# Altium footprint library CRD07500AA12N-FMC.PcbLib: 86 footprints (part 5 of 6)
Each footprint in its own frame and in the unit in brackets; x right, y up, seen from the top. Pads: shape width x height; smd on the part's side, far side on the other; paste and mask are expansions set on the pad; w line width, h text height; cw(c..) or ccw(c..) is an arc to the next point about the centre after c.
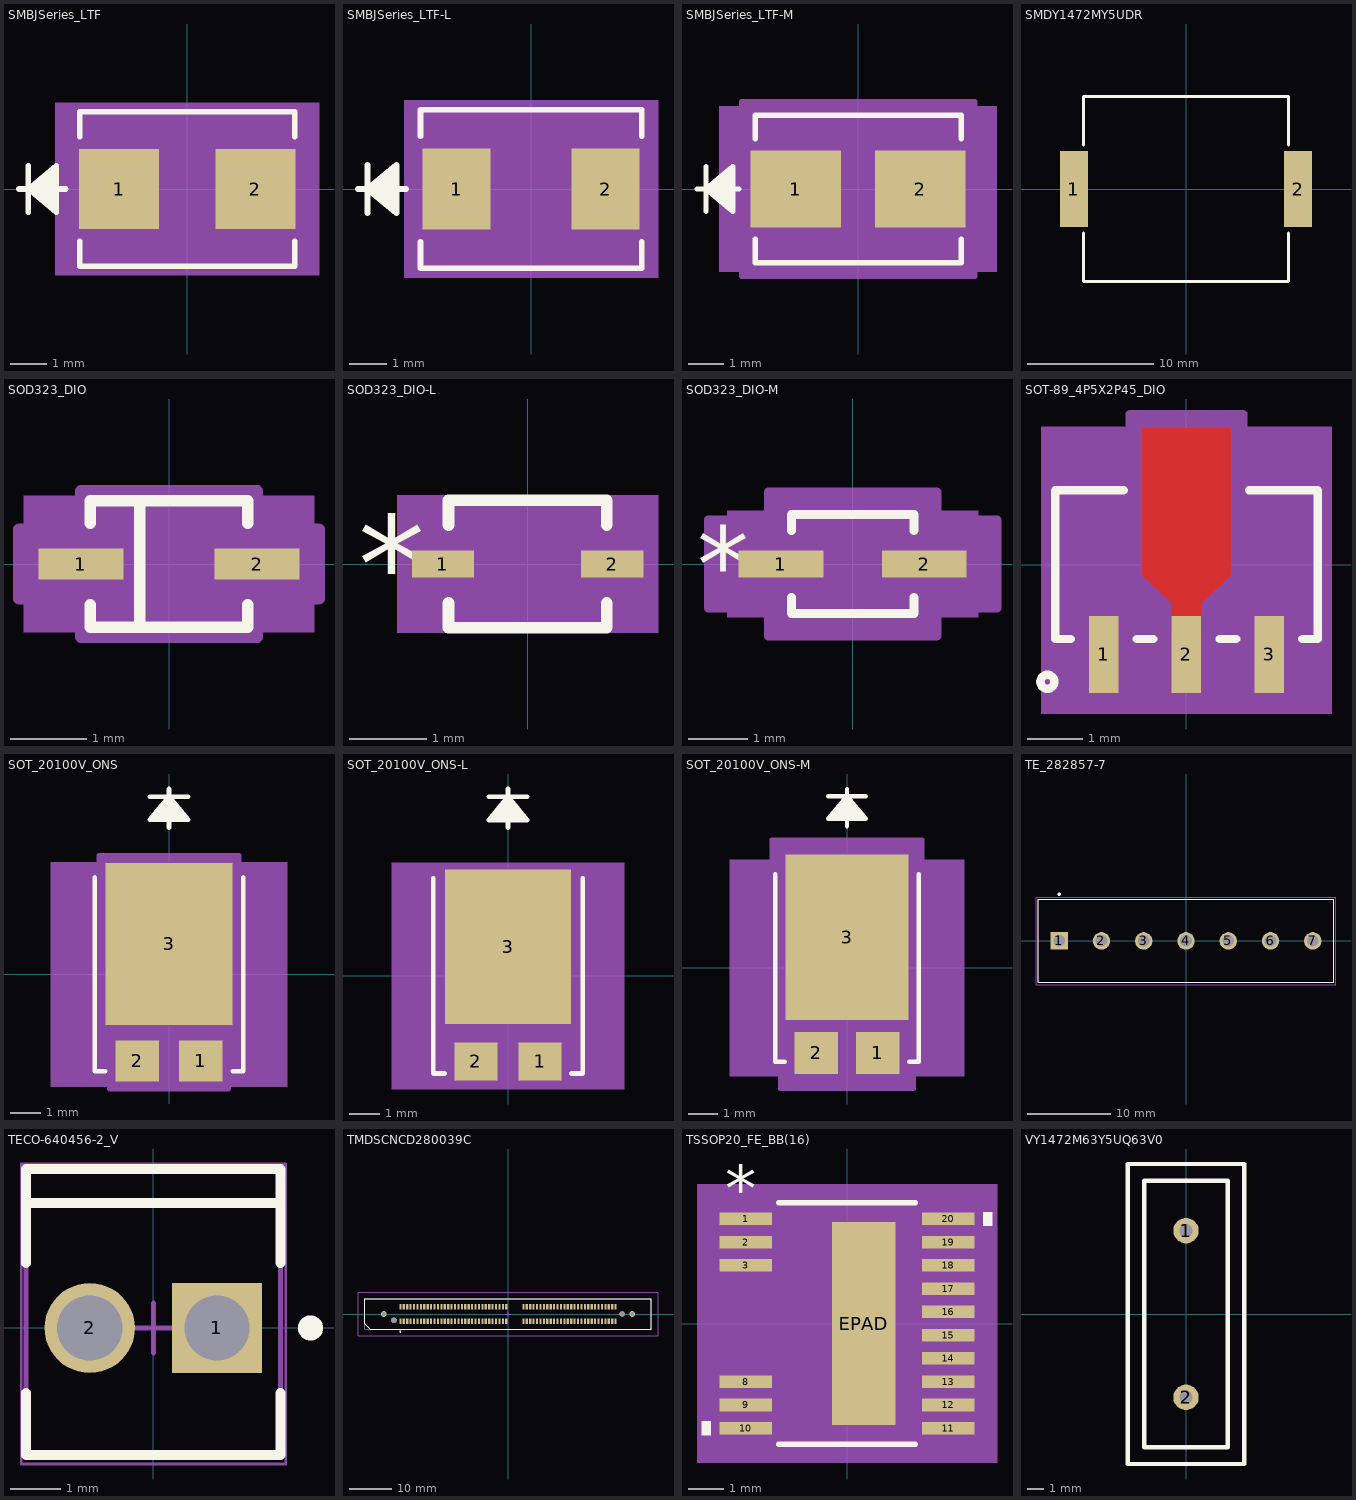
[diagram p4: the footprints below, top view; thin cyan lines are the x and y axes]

## SMBJSeries_LTF [mil]
pads (2):
  rect 86x86 smd paste+0 mask+0: 1(-73,0) 2(73,0)
Top Overlay:
  lines w6: -180,0 -130,0 ; -170,-25 -170,25 ; -140,-20 -170,0 ; -140,-15 -170,0 ; -140,-10 -170,0 ; -140,-5 -170,0 ; -140,5 -170,0 ; -140,10 -170,0 ; -140,15 -170,0 ; -140,20 -170,0 ; -115,-56.1 -115,-82.5 115,-82.5 115,-56.1 ; -115,56.1 -115,82.5 115,82.5 115,56.1 ; -170,0 -140,-25 -140,25 -170,0
Mechanical 5:
  region: 141,-92.5 -141,-92.5 -141,92.5 141,92.5
Mechanical 13:
  lines w1: -180,0 -130,0 ; -170,-25 -170,25 ; -140,-20 -170,0 ; -140,-15 -170,0 ; -140,-10 -170,0 ; -140,-5 -170,0 ; -140,5 -170,0 ; -140,10 -170,0 ; -140,15 -170,0 ; -140,20 -170,0 ; -170,0 -140,-25 -140,25 -170,0 ; -110,-77.5 -110,77.5 110,77.5 110,-77.5 -110,-77.5
Mechanical 15:
  region: -120,-53 -126,-53 -126,53 -120,53 -120,87.5 120,87.5 120,53 126,53 126,-53 120,-53 120,-87.5 -120,-87.5
  lines w6: -126,-53 -120,-53 -120,-87.5 120,-87.5 120,-53 126,-53 126,53 120,53 120,87.5 -120,87.5 -120,53 -126,53 -126,-53
3D body "SMBJSeries_LTF.step": height 97.99, standoff 0, extent -110,-77.48 110,77.48

## SMBJSeries_LTF-L [mil]
pads (2):
  rect 71x84 smd paste+0 mask+0: 1(-77.5,0) 2(77.5,0)
Top Overlay:
  lines w6: -180,0 -130,0 ; -170,-25 -170,25 ; -140,-20 -170,0 ; -140,-15 -170,0 ; -140,-10 -170,0 ; -140,-5 -170,0 ; -140,5 -170,0 ; -140,10 -170,0 ; -140,15 -170,0 ; -140,20 -170,0 ; -115,-54.95 -115,-82.5 115,-82.5 115,-54.95 ; -115,54.95 -115,82.5 115,82.5 115,54.95 ; -170,0 -140,25 -140,-25 -170,0
Mechanical 5:
  region: 132,-92.5 -132,-92.5 -132,92.5 132,92.5
Mechanical 13:
  lines w1: -180,0 -130,0 ; -170,-25 -170,25 ; -140,-20 -170,0 ; -140,-15 -170,0 ; -140,-10 -170,0 ; -140,-5 -170,0 ; -140,5 -170,0 ; -140,10 -170,0 ; -140,15 -170,0 ; -140,20 -170,0 ; -170,0 -140,25 -140,-25 -170,0 ; -110,-77.5 110,-77.5 110,77.5 -110,77.5 -110,-77.5
Mechanical 15:
  region: -114,-47 -117,-47 -117,47 -114,47 -114,81.5 114,81.5 114,47 117,47 117,-47 114,-47 114,-81.5 -114,-81.5
  lines w6: -117,-47 -117,47 -114,47 -114,81.5 114,81.5 114,47 117,47 117,-47 114,-47 114,-81.5 -114,-81.5 -114,-47 -117,-47
3D body "SMBJSeries_LTF.step": height 97.99, standoff 0, extent -110,-77.48 110,77.48

## SMBJSeries_LTF-M [mil]
pads (2):
  rect 101x86 smd paste+0 mask+0: 1(-69.5,0) 2(69.5,0)
Top Overlay:
  lines w6: -180,0 -133.1,0 ; -170,-25 -170,25 ; -140,-20 -170,0 ; -140,-15 -170,0 ; -140,-10 -170,0 ; -140,-5 -170,0 ; -140,5 -170,0 ; -140,10 -170,0 ; -140,15 -170,0 ; -140,20 -170,0 ; -115,-56.1 -115,-82.5 115,-82.5 115,-56.1 ; -115,56.1 -115,82.5 115,82.5 115,56.1 ; -170,0 -140,-25 -140,25 -170,0
Mechanical 5:
  region: 155,-92.5 -155,-92.5 -155,92.5 155,92.5
Mechanical 13:
  lines w1: -180,0 -130,0 ; -170,-25 -170,25 ; -140,-20 -170,0 ; -140,-15 -170,0 ; -140,-10 -170,0 ; -140,-5 -170,0 ; -140,5 -170,0 ; -140,10 -170,0 ; -140,15 -170,0 ; -140,20 -170,0 ; -170,0 -140,-25 -140,25 -170,0 ; -110,-77.5 -110,77.5 110,77.5 110,-77.5 -110,-77.5
Mechanical 15:
  region: -130,-63 -140,-63 -140,63 -130,63 -130,97.5 130,97.5 130,63 140,63 140,-63 130,-63 130,-97.5 -130,-97.5
  lines w6: -140,-63 -130,-63 -130,-97.5 130,-97.5 130,-63 140,-63 140,63 130,63 130,97.5 -130,97.5 -130,63 -140,63 -140,-63
3D body "SMBJSeries_LTF.step": height 97.99, standoff 0, extent -110,-77.48 110,77.48

## SMDY1472MY5UDR [mm]
pads (2):
  rect 2.2x6 smd: 1(-8.85,0) 2(8.85,0)
Top Overlay:
  lines w0.254: -8.1,-3.5 -8.1,-7.3 8.1,-7.3 8.1,-3.5 ; -8.1,3.5 -8.1,7.3 8.1,7.3 8.1,3.5
3D body "Vishay SMDY1472MY5UD#.stp": height 4.15, standoff 0.05, extent -9.6,-7.3 9.6,7.3

## SOD323_DIO [mm]
pads (2):
  rect 1.111x0.401 smd paste+0 mask+0: 1(-1.15,0) 2(1.15,0)
Top Overlay:
  lines w0.152: -1.027,-0.533 -1.027,-0.827 1.027,-0.827 1.027,-0.533 ; -1.027,0.533 -1.027,0.827 1.027,0.827 1.027,0.533 ; -0.381,-0.762 -0.381,0.762
Mechanical 5:
  region: 1.896,-0.891 -1.896,-0.891 -1.896,0.891 1.896,0.891
Mechanical 13:
  lines w0.025: -0.9,-0.35 -0.55,-0.7 ; -0.9,0.35 -0.55,0.7 ; -1.35,-0.175 -0.9,-0.175 -0.9,0.175 -1.35,0.175 -1.35,-0.175 ; -0.9,-0.7 -0.9,0.7 0.9,0.7 0.9,-0.7 -0.9,-0.7 ; 0.9,-0.175 1.35,-0.175 1.35,0.175 0.9,0.175 0.9,-0.175
  text "*" at -0.964,-0.635 h1.27
Mechanical 15:
  region: -1.154,-0.454 -1.96,-0.454 -1.96,0.454 -1.154,0.454 -1.154,0.954 1.154,0.954 1.154,0.454 1.96,0.454 1.96,-0.454 1.154,-0.454 1.154,-0.954 -1.154,-0.954
  lines w0.152: -1.96,-0.454 -1.154,-0.454 -1.154,-0.954 1.154,-0.954 1.154,-0.454 1.96,-0.454 1.96,0.454 1.154,0.454 1.154,0.954 -1.154,0.954 -1.154,0.454 -1.96,0.454 -1.96,-0.454
3D body "SOD323_DIO.step": height 0.81, standoff 0, extent -1.35,-0.7 1.35,0.7

## SOD323_DIO-L [mm]
pads (2):
  rect 0.806x0.35 smd paste+0 mask+0: 1(-1.099,0) 2(1.099,0)
Top Overlay:
  lines w0.152: -1.027,-0.508 -1.027,-0.827 1.027,-0.827 1.027,-0.508 ; -1.027,0.508 -1.027,0.827 1.027,0.827 1.027,0.508
  text "*" at -2.201,-0.635 h1.27
Mechanical 5:
  region: 1.693,-0.891 -1.693,-0.891 -1.693,0.891 1.693,0.891
Mechanical 13:
  lines w0.025: -0.9,-0.35 -0.55,-0.7 ; -0.9,0.35 -0.55,0.7 ; -1.35,-0.175 -1.35,0.175 -0.9,0.175 -0.9,-0.175 -1.35,-0.175 ; -0.9,-0.7 0.9,-0.7 0.9,0.7 -0.9,0.7 -0.9,-0.7 ; 0.9,-0.175 0.9,0.175 1.35,0.175 1.35,-0.175 0.9,-0.175
  text "*" at -0.964,-0.635 h1.27
Mechanical 15:
  region: -1.002,-0.277 -1.604,-0.277 -1.604,0.277 -1.002,0.277 -1.002,0.802 1.002,0.802 1.002,0.277 1.604,0.277 1.604,-0.277 1.002,-0.277 1.002,-0.802 -1.002,-0.802
  lines w0.152: -1.604,-0.277 -1.604,0.277 -1.002,0.277 -1.002,0.802 1.002,0.802 1.002,0.277 1.604,0.277 1.604,-0.277 1.002,-0.277 1.002,-0.802 -1.002,-0.802 -1.002,-0.277 -1.604,-0.277
3D body "SOD323_DIO.step": height 0.81, standoff 0, extent -1.35,-0.7 1.35,0.7

## SOD323_DIO-M [mm]
pads (2):
  rect 1.416x0.452 smd paste+0 mask+0: 1(-1.201,0) 2(1.201,0)
Top Overlay:
  lines w0.152: -1.027,-0.559 -1.027,-0.827 1.027,-0.827 1.027,-0.559 ; -1.027,0.559 -1.027,0.827 1.027,0.827 1.027,0.559
  text "*" at -2.607,-0.635 h1.27
Mechanical 5:
  region: 2.099,-0.891 -2.099,-0.891 -2.099,0.891 2.099,0.891
Mechanical 13:
  lines w0.025: -0.9,-0.35 -0.55,-0.7 ; -0.9,0.35 -0.55,0.7 ; -1.35,-0.175 -1.35,0.175 -0.9,0.175 -0.9,-0.175 -1.35,-0.175 ; -0.9,-0.7 0.9,-0.7 0.9,0.7 -0.9,0.7 -0.9,-0.7 ; 0.9,-0.175 0.9,0.175 1.35,0.175 1.35,-0.175 0.9,-0.175
  text "*" at -0.964,-0.635 h1.27
Mechanical 15:
  region: -1.408,-0.734 -2.417,-0.734 -2.417,0.734 -1.408,0.734 -1.408,1.208 1.408,1.208 1.408,0.734 2.417,0.734 2.417,-0.734 1.408,-0.734 1.408,-1.208 -1.408,-1.208
  lines w0.152: -2.417,-0.734 -2.417,0.734 -1.408,0.734 -1.408,1.208 1.408,1.208 1.408,0.734 2.417,0.734 2.417,-0.734 1.408,-0.734 1.408,-1.208 -1.408,-1.208 -1.408,-0.734 -2.417,-0.734
3D body "SOD323_DIO.step": height 0.81, standoff 0, extent -1.35,-0.7 1.35,0.7

## SOT-89_4P5X2P45_DIO [mil]
pads (3):
  rect 21x55 smd paste+0 mask+0: 1(-59.06,-64) 2(0,-64) 3(59.06,-64)
Top Layer:
  region: 10.5,-48 -10.5,-48 -10.5,-27.5 -31.5,-7.5 -31.5,97.5 -16.25,97.5 16.25,97.5 31.5,97.5 31.5,-7.5 10.5,-27.5
Top Overlay:
  circle w6: c-99.21,-83.5 r5
  lines w6: -82.66,-53 -93.58,-53 -93.58,53 -44.6,53 ; -35.46,-53 -23.6,-53 ; 23.6,-53 35.46,-53 ; 44.6,53 93.58,53 93.58,-53 82.66,-53
Top Paste:
  region: 10.5,-48 -10.5,-48 -10.5,-27.5 -31.5,-7.5 -31.5,97.5 31.5,97.5 31.5,-7.5 10.5,-27.5
Top Solder:
  region: 10.5,-48 -10.5,-48 -10.5,-27.5 -31.5,-7.5 -31.5,97.5 31.5,97.5 31.5,-7.5 10.5,-27.5
Mechanical 5:
  region: -103.58,98.5 103.58,98.5 103.58,-106.5 -103.58,-106.5
Mechanical 13:
  circle w0: c-78.58,-38 r5
  lines w1: -88.58,-48 -88.58,48 88.58,48 88.58,-48 -88.58,-48 ; -69.56,-95 -48.56,-95 -48.56,-48 -69.56,-48 -69.56,-95 ; -10.5,-95 10.5,-95 10.5,-48 -10.5,-48 -10.5,-95 ; 48.56,-95 69.56,-95 69.56,-48 48.56,-48 48.56,-95
Mechanical 15:
  region: -98.58,-58 -98.58,58 -40.5,58 -40.5,107.5 40.5,107.5 40.5,58 98.58,58 98.58,-58 79.06,-58 79.06,-101.5 -79.06,-101.5 -79.06,-58
  lines w6: -98.58,-58 -79.06,-58 -79.06,-101.5 79.06,-101.5 79.06,-58 98.58,-58 98.58,58 40.5,58 40.5,107.5 -40.5,107.5 -40.5,58 -98.58,58 -98.58,-58
3D body: height 10, standoff 0, extent 0,0 10,10
3D body "SOT-89-3.step": height 66.93, standoff 0, extent -92.5,-88.58 92.5,86.62

## SOT_20100V_ONS [mil]
pads (3):
  rect 57x53 smd paste+0 mask+0: 1(41.34,-112.5) 2(-41.34,-112.5)
  rect 165x211 smd paste+0 mask+0: 3(0,39.5)
Top Overlay:
  lines w6: -96.5,126 -96.5,-126 -82.94,-126 ; -25,231 25,231 ; -20,201 0,231 ; -15,201 0,231 ; -10,201 0,231 ; -5,201 0,231 ; 0,191 0,241 ; 5,201 0,231 ; 10,201 0,231 ; 15,201 0,231 ; 20,201 0,231 ; 82.94,-126 96.5,-126 96.5,126 ; 0,231 25,201 -25,201 0,231
Mechanical 5:
  region: 154,-146 -154,-146 -154,146 154,146
Mechanical 13:
  lines w1: -25,231 25,231 ; -20,201 0,231 ; -15,201 0,231 ; -10,201 0,231 ; -5,201 0,231 ; 0,191 0,241 ; 5,201 0,231 ; 10,201 0,231 ; 15,201 0,231 ; 20,201 0,231 ; 0,231 25,201 -25,201 0,231 ; -91.5,-121 91.5,-121 91.5,121 -91.5,121 -91.5,-121
Mechanical 15:
  region: -77.84,-131 -101.5,-131 -101.5,131 -91.5,131 -91.5,155 91.5,155 91.5,131 101.5,131 101.5,-131 77.84,-131 77.84,-149 -77.84,-149
  region: 91.5,-121 -91.5,-121 -91.5,121 91.5,121
  lines w6: -101.5,-131 -101.5,131 -91.5,131 -91.5,155 91.5,155 91.5,131 101.5,131 101.5,-131 77.84,-131 77.84,-149 -77.84,-149 -77.84,-131 -101.5,-131
3D body "SOT_20100V_ONS.step": height 49.09, standoff 0, extent -91.5,-130.98 91.5,130.98

## SOT_20100V_ONS-L [mil]
pads (3):
  rect 55x49 smd paste+0 mask+0: 1(41.34,-110.5) 2(-41.34,-110.5)
  rect 163x199 smd paste+0 mask+0: 3(0,37.5)
Top Overlay:
  lines w6: -96.5,126 -96.5,-126 -81.94,-126 ; -25,231 25,231 ; -20,201 0,231 ; -15,201 0,231 ; -10,201 0,231 ; -5,201 0,231 ; 0,191 0,241 ; 5,201 0,231 ; 10,201 0,231 ; 15,201 0,231 ; 20,201 0,231 ; 81.94,-126 96.5,-126 96.5,126 ; 0,231 25,201 -25,201 0,231
Mechanical 5:
  region: 150,-146 -150,-146 -150,146 150,146
Mechanical 13:
  lines w1: -25,231 25,231 ; -20,201 0,231 ; -15,201 0,231 ; -10,201 0,231 ; -5,201 0,231 ; 0,191 0,241 ; 5,201 0,231 ; 10,201 0,231 ; 15,201 0,231 ; 20,201 0,231 ; 0,231 25,201 -25,201 0,231 ; -91.5,-121 91.5,-121 91.5,121 -91.5,121 -91.5,-121
Mechanical 15:
  region: -69.84,-125 -95.5,-125 -95.5,125 -85.5,125 -85.5,141 85.5,141 85.5,125 95.5,125 95.5,-125 69.84,-125 69.84,-139 -69.84,-139
  region: 91.5,-121 -91.5,-121 -91.5,121 91.5,121
  lines w6: -95.5,-125 -95.5,125 -85.5,125 -85.5,141 85.5,141 85.5,125 95.5,125 95.5,-125 69.84,-125 69.84,-139 -69.84,-139 -69.84,-125 -95.5,-125
3D body "SOT_20100V_ONS.step": height 49.09, standoff 0, extent -91.5,-130.98 91.5,130.98

## SOT_20100V_ONS-M [mil]
pads (3):
  rect 59x57 smd paste+0 mask+0: 1(41.34,-114.5) 2(-41.34,-114.5)
  rect 165x223 smd paste+0 mask+0: 3(0,41.5)
Top Overlay:
  lines w6: -96.5,126 -96.5,-126 -83.94,-126 ; -25,231 25,231 ; -20,201 0,231 ; -15,201 0,231 ; -10,201 0,231 ; -5,201 0,231 ; 0,191 0,241 ; 5,201 0,231 ; 10,201 0,231 ; 15,201 0,231 ; 20,201 0,231 ; 83.94,-126 96.5,-126 96.5,126 ; 0,231 -25,201 25,201 0,231
Mechanical 5:
  region: 158,-146 -158,-146 -158,146 158,146
Mechanical 13:
  lines w1: -25,231 25,231 ; -20,201 0,231 ; -15,201 0,231 ; -10,201 0,231 ; -5,201 0,231 ; 0,191 0,241 ; 5,201 0,231 ; 10,201 0,231 ; 15,201 0,231 ; 20,201 0,231 ; 0,231 -25,201 25,201 0,231 ; -91.5,-121 -91.5,121 91.5,121 91.5,-121 -91.5,-121
Mechanical 15:
  region: 91.5,-121 -91.5,-121 -91.5,121 91.5,121
  region: -89.84,-141 -111.5,-141 -111.5,141 -101.5,141 -101.5,173 101.5,173 101.5,141 111.5,141 111.5,-141 89.84,-141 89.84,-163 -89.84,-163
  lines w6: -111.5,-141 -89.84,-141 -89.84,-163 89.84,-163 89.84,-141 111.5,-141 111.5,141 101.5,141 101.5,173 -101.5,173 -101.5,141 -111.5,141 -111.5,-141
3D body "SOT_20100V_ONS.step": height 49.09, standoff 0, extent -91.5,-130.98 91.5,130.98

## TE_282857-7 [mm]
pads (7):
  rect 2.1x2.1 hole 1.4: 1(-15.24,0)
  round 2.1 hole 1.4: 2(-10.16,0) 3(-5.08,0) 4(0,0) 5(5.08,0) 6(10.16,0) 7(15.24,0)
Top Overlay:
  circle w0.2: c-15.24,5.6 r0.1
  lines w0.127: -17.78,-5 -17.78,5 17.78,5 17.78,-5 -17.78,-5
Mechanical 13:
  circle w0.2: c-15.24,5.6 r0.1
  lines w0.127: -17.78,-5 -17.78,5 17.78,5 17.78,-5 -17.78,-5
Mechanical 15:
  lines w0.05: -18.03,-5.25 -18.03,5.25 18.03,5.25 18.03,-5.25 -18.03,-5.25
3D body "step_temp.STEP": height 19.05, standoff -3.45, extent -18.28,-5 17.78,5

## TECO-640456-2_V [mm] "HDR, 2-Leads, Body 5.715x5.08mm, Pitch 2.54mm"
height 10.49
pads (2):
  rect 1.8x1.8 hole 1.3: 1(1.27,0)
  round 1.8 hole 1.3: 2(-1.27,0)
Top Overlay:
  circle w0.25: c3.14,0 r0.125
  lines w0.2: -2.54,-1.3 -2.54,-2.54 2.54,-2.54 2.54,-1.3 ; -2.54,1.3 -2.54,3.175 2.54,3.175 2.54,1.3 ; -2.54,2.5 2.54,2.5
Mechanical 13:
  lines w0.1: -2.54,-2.54 -2.54,3.175 2.54,3.175 2.54,-2.54 -2.54,-2.54
Mechanical 15:
  lines w0.05: -2.64,-2.717 2.64,-2.717 2.64,3.275 -2.64,3.275 -2.64,-2.717
  lines w0.1: -0.5,0 0.5,0 ; 0,-0.5 0,0.5
3D body "TE 640456-2 Color.STEP": height 10.09, standoff -3.5, extent -2.54,-2.667 2.54,3.175

## TMDSCNCD280039C [mm]
pads (124):
  rect 0.5x1.2 smd paste+0 mask+0: 1(25.2,1.7) 2(25.2,-1.7) 3(24.4,1.7) 4(24.4,-1.7) 5(23.6,1.7) 6(23.6,-1.7) 7(22.8,1.7) 8(22.8,-1.7) 9(22,1.7) 10(22,-1.7) 11(21.2,1.7) 12(21.2,-1.7) 13(20.4,1.7) 14(20.4,-1.7) 15(19.6,1.7) 16(19.6,-1.7) 17(18.8,1.7) 18(18.8,-1.7) 19(18,1.7) 20(18,-1.7) 21(17.2,1.7) 22(17.2,-1.7) 23(16.4,1.7) 24(16.4,-1.7) 25(15.6,1.7) 26(15.6,-1.7) 27(14.8,1.7) 28(14.8,-1.7) 29(14,1.7) 30(14,-1.7) 31(13.2,1.7) 32(13.2,-1.7) 33(12.4,1.7) 34(12.4,-1.7) 35(11.6,1.7) 36(11.6,-1.7) 37(10.8,1.7) 38(10.8,-1.7) 39(10,1.7) 40(10,-1.7) 41(9.2,1.7) 42(9.2,-1.7) 43(8.4,1.7) 44(8.4,-1.7) 45(7.6,1.7) 46(7.6,-1.7) 47(6.8,1.7) 48(6.8,-1.7) 49(6,1.7) 50(6,-1.7) 51(5.2,1.7) 52(5.2,-1.7) 53(4.4,1.7) 54(4.4,-1.7) 55(3.6,1.7) 56(3.6,-1.7) 57(-0.4,1.7) 58(-0.4,-1.7) 59(-1.2,1.7) 60(-1.2,-1.7) 61(-2,1.7) 62(-2,-1.7) 63(-2.8,1.7) 64(-2.8,-1.7) 65(-3.6,1.7) 66(-3.6,-1.7) 67(-4.4,1.7) 68(-4.4,-1.7) 69(-5.2,1.7) 70(-5.2,-1.7) 71(-6,1.7) 72(-6,-1.7) 73(-6.8,1.7) 74(-6.8,-1.7) 75(-7.6,1.7) 76(-7.6,-1.7) 77(-8.4,1.7) 78(-8.4,-1.7) 79(-9.2,1.7) 80(-9.2,-1.7) 81(-10,1.7) 82(-10,-1.7) 83(-10.8,1.7) 84(-10.8,-1.7) 85(-11.6,1.7) 86(-11.6,-1.7) 87(-12.4,1.7) 88(-12.4,-1.7) 89(-13.2,1.7) 90(-13.2,-1.7) 91(-14,1.7) 92(-14,-1.7) 93(-14.8,1.7) 94(-14.8,-1.7) 95(-15.6,1.7) 96(-15.6,-1.7) 97(-16.4,1.7) 98(-16.4,-1.7) 99(-17.2,1.7) 100(-17.2,-1.7) 101(-18,1.7) 102(-18,-1.7) 103(-18.8,1.7) 104(-18.8,-1.7) 105(-19.6,1.7) 106(-19.6,-1.7) 107(-20.4,1.7) 108(-20.4,-1.7) 109(-21.2,1.7) 110(-21.2,-1.7) 111(-22,1.7) 112(-22,-1.7) 113(-22.8,1.7) 114(-22.8,-1.7) 115(-23.6,1.7) 116(-23.6,-1.7) 117(-24.4,1.7) 118(-24.4,-1.7) 119(-25.2,1.7) 120(-25.2,-1.7)
  round 1.34 hole 0.84 paste-1000 mask+0: 121(-29.05,0) 122(29.05,0)
  round 1.27 hole 1.27 unplated paste-1000 mask+0: ""(-26.7,-1.5) ""(26.7,0)
Top Overlay:
  circle w0.25: c-25.2,-4.125 r0.125
  lines w0.2: -33.55,-2.295 -32.28,-3.565 33.55,-3.565 33.55,3.565 -33.55,3.565 -33.55,-2.295
Top Paste:
  circle w1.27: c29.05,0 r0.635
  circle w1.27: c-29.05,0 r0.635
Mechanical 5:
  lines w0.2: -35.115,-5.09 -35.115,5.09 35.115,5.09 35.115,-5.09 -35.115,-5.09
  text ".Designator" at 0,0.188 h1
Mechanical 13:
  lines w0.2: -33.55,-3.565 -33.55,3.565 33.55,3.565 33.55,-3.565 -33.55,-3.565
Mechanical 15:
  lines w0.2: -35.115,-5.09 -35.115,5.09 35.115,5.09 35.115,-5.09 -35.115,-5.09
Mechanical 16:
  lines w0.1: -0.5,0 0.5,0 ; 0,-0.5 0,0.5
3D body "Samtec HSEC8-160-01-L-DV-A-BL.stp": height 12.4, standoff -1.3, extent -33.525,-3.5 33.525,3.5
3D body "TI TMS320F280039C.step": height 57.35, standoff 2, extent -33.874,-4.89 34.671,5.68

## TSSOP20_FE_BB(16) [mm]
pads (17):
  rect 1.461x0.351 smd paste+0 mask+0: 1(-2.825,2.925) 2(-2.825,2.275) 3(-2.825,1.625) 8(-2.825,-1.625) 9(-2.825,-2.275) 10(-2.825,-2.925) 11(2.825,-2.925) 12(2.825,-2.275) 13(2.825,-1.625) 14(2.825,-0.975) 15(2.825,-0.325) 16(2.825,0.325) 17(2.825,0.975) 18(2.825,1.625) 19(2.825,2.275) 20(2.825,2.925)
  rect 1.78x5.68 smd paste-2.827 mask+0: EPAD(0.47,0)
Top Overlay:
  region: -3.81,-2.734 -4.064,-2.734 -4.064,-3.115 -3.81,-3.115
  region: 3.81,3.115 4.064,3.115 4.064,2.734 3.81,2.734
  lines w0.152: -1.909,-3.377 1.909,-3.377 ; -1.909,3.377 1.909,3.377
  text "*" at -3.397,3.149 h1.27
Top Paste:
  region: 1.26,2.74 -0.32,2.74 -0.32,1.52 1.26,1.52
  region: 1.26,1.32 -0.32,1.32 -0.32,0.1 1.26,0.1
  region: 1.26,-0.1 -0.32,-0.1 -0.32,-1.32 1.26,-1.32
  region: 1.26,-1.52 -0.32,-1.52 -0.32,-2.74 1.26,-2.74
Mechanical 5:
  region: 4.191,-3.885 -4.191,-3.885 -4.191,3.885 4.191,3.885
Mechanical 13:
  lines w0: -0.305,3.25 ccw(c0,3.25) 0.305,3.25
  lines w0.025: -3.2,-3.075 -3.2,-2.775 -2.2,-2.775 -2.2,-3.075 -3.2,-3.075 ; -3.2,-2.425 -3.2,-2.125 -2.2,-2.125 -2.2,-2.425 -3.2,-2.425 ; -3.2,-1.775 -3.2,-1.475 -2.2,-1.475 -2.2,-1.775 -3.2,-1.775 ; -3.2,1.475 -3.2,1.775 -2.2,1.775 -2.2,1.475 -3.2,1.475 ; -3.2,2.125 -3.2,2.425 -2.2,2.425 -2.2,2.125 -3.2,2.125 ; -3.2,2.775 -3.2,3.075 -2.2,3.075 -2.2,2.775 -3.2,2.775 ; -2.2,-3.25 2.2,-3.25 2.2,3.25 -2.2,3.25 -2.2,-3.25 ; 2.2,-3.075 2.2,-2.775 3.2,-2.775 3.2,-3.075 2.2,-3.075 ; 2.2,-2.425 2.2,-2.125 3.2,-2.125 3.2,-2.425 2.2,-2.425 ; 2.2,-1.775 2.2,-1.475 3.2,-1.475 3.2,-1.775 2.2,-1.775 ; 2.2,-1.125 2.2,-0.825 3.2,-0.825 3.2,-1.125 2.2,-1.125 ; 2.2,-0.475 2.2,-0.175 3.2,-0.175 3.2,-0.475 2.2,-0.475 ; 2.2,0.175 2.2,0.475 3.2,0.475 3.2,0.175 2.2,0.175 ; 2.2,0.825 2.2,1.125 3.2,1.125 3.2,0.825 2.2,0.825 ; 2.2,1.475 2.2,1.775 3.2,1.775 3.2,1.475 2.2,1.475 ; 2.2,2.125 2.2,2.425 3.2,2.425 3.2,2.125 2.2,2.125 ; 2.2,2.775 2.2,3.075 3.2,3.075 3.2,2.775 2.2,2.775
  text "*" at -2.137,1.904 h1.27
Mechanical 15:
  region: -2.454,-3.354 -3.81,-3.354 -3.81,3.354 -2.454,3.354 -2.454,3.504 2.454,3.504 2.454,3.354 3.81,3.354 3.81,-3.354 2.454,-3.354 2.454,-3.504 -2.454,-3.504
  lines w0.152: -3.81,-3.354 -3.81,3.354 -2.454,3.354 -2.454,3.504 2.454,3.504 2.454,3.354 3.81,3.354 3.81,-3.354 2.454,-3.354 2.454,-3.504 -2.454,-3.504 -2.454,-3.354 -3.81,-3.354
3D body "20-TSSOP (16-LEADS, EXPOSED PAD).STEP": height 1.2, standoff -0.05, extent -3.2,-3.302 3.2,3.302
3D body: height 0.25, standoff 0, extent 0,0 0.254,0.254

## VY1472M63Y5UQ63V0 [mm] "4700pF 760VAC Y1"
pads (2):
  round 1.524 hole 0.8: 1(0,5) 2(0,-5)
Top Overlay:
  lines w0.254: -3.5,-9 3.5,-9 3.5,9 -3.5,9 -3.5,-9 ; -2.5,-8 2.5,-8 2.5,8 -2.5,8 -2.5,-8
3D body "User Library-Y1222 (Ycap).STEP": height 9, standoff -3.5, extent -3.597,-5.435 3.597,5.688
